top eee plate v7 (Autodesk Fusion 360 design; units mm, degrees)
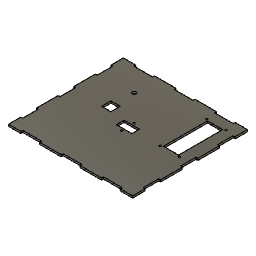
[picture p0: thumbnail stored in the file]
sketch "Sketch1" plane through (0, 0, 0) normal (0, 0, 1) x axis (1, 0, 0)
  line L1 (-100, 92.5) -> (100, 92.5)
  line L2 (-100, -92.5) -> (-100, 92.5)
  line L3 (100, -92.5) -> (-100, -92.5)
  line L4 (100, 92.5) -> (100, -92.5)
  line L5 (-100, -92.5) -> (100, 92.5)
  line L6 (100, -92.5) -> (-100, 92.5)
  point P6 (0, 0)
  point P1 (0, 0)
  point P4 (-100, -92.5)
  point P5 (100, -92.5)
  point P3 (-100, 92.5)
  point P2 (100, 92.5)
  perpendicular L1 L2
  parallel L1 L3
  parallel L2 L4
  horizontal L1
  coincident L5 P6
  coincident L6 P6
  coincident P1 P6
  dimension "d1" distance P4 P5 = 200
  dimension "d2" distance P3 P4 = 185
  dimension "d28" distance P2 = 15
extrude "Extrude1" new body sketch "Sketch1" profile of L1 L2 L3 L4 along normal blind 3
sketch "Sketch2" plane through (0, 0, 3) normal (0, 0, 1) x axis (-1, 0, 0)
  line L1 (-100, -92.5) -> (-100, 92.5)
  line L2 (100, -92.5) -> (-100, -92.5)
  line L3 (100, 92.5) -> (100, -92.5)
  line L4 (50, 92.5) -> (80, 92.5)
  line L5 (50, 89.5) -> (50, 92.5)
  line L6 (80, 89.5) -> (50, 89.5)
  line L7 (80, 92.5) -> (80, 89.5)
  line L8 (-15, 92.5) -> (15, 92.5)
  line L9 (-15, 89.5) -> (-15, 92.5)
  line L10 (15, 89.5) -> (-15, 89.5)
  line L11 (15, 92.5) -> (15, 89.5)
  line L12 (-80, 92.5) -> (-50, 92.5)
  line L13 (-80, 89.5) -> (-80, 92.5)
  line L14 (-50, 89.5) -> (-80, 89.5)
  line L15 (-50, 92.5) -> (-50, 89.5)
  line L16 (-100, 92.5) -> (100, 92.5)
  point P6 (80, 92.5)
  point P9 (80, 89.5)
  point P18 (100, 92.5)
  point P7 (50, 92.5)
  point P10 (15, 92.5)
  point P11 (-15, 92.5)
  point P12 (-15, 89.5)
  point P14 (-50, 92.5)
  point P15 (-80, 92.5)
  point P19 (-100, 92.5)
  horizontal L4
  vertical L5
  horizontal L6
  vertical L7
  horizontal L8
  vertical L9
  horizontal L10
  vertical L11
  horizontal L12
  vertical L13
  horizontal L14
  vertical L15
  equal L7 L11
  equal L11 L15
  collinear L8 L12
  collinear L8 L16
  collinear L4 L16
  dimension "d5" distance P6 P9 = 3
  dimension "d6" distance P6 P18 = 20
  dimension "d7" distance P6 P7 = 30
  dimension "d8" distance P7 P10 = 35
  dimension "d9" distance P10 P11 = 30
  dimension "d10" distance P12 P14 = 35
  dimension "d11" distance P14 P15 = 30
  dimension "d12" distance P15 P19 = 20
extrude "Extrude2" cut sketch "Sketch2" profile of L4 L5 L6 L7 L8 L9 L10 L11 L12 L13 L14 L15 L16 against normal blind 20
mirror "Mirror1"
sketch "Sketch3" plane through (0, 0, 3) normal (0, 0, 1) x axis (-1, 0, 0)
  line L1 (50, -89.5) -> (50, -92.5)
  line L2 (80, -89.5) -> (50, -89.5)
  line L3 (80, -92.5) -> (80, -89.5)
  line L4 (100, -92.5) -> (80, -92.5)
  line L5 (100, 92.5) -> (100, -92.5)
  line L6 (80, 92.5) -> (100, 92.5)
  line L7 (80, 89.5) -> (80, 92.5)
  line L8 (50, 89.5) -> (80, 89.5)
  line L9 (50, 92.5) -> (50, 89.5)
  line L10 (15, 92.5) -> (50, 92.5)
  line L11 (15, 89.5) -> (15, 92.5)
  line L12 (-15, 89.5) -> (15, 89.5)
  line L13 (-15, 92.5) -> (-15, 89.5)
  line L14 (-50, 92.5) -> (-15, 92.5)
  line L15 (-50, 89.5) -> (-50, 92.5)
  line L16 (-80, 89.5) -> (-50, 89.5)
  line L17 (-80, 92.5) -> (-80, 89.5)
  line L18 (-100, 92.5) -> (-80, 92.5)
  line L19 (-100, -92.5) -> (-100, 92.5)
  line L20 (-80, -92.5) -> (-100, -92.5)
  line L21 (-80, -89.5) -> (-80, -92.5)
  line L22 (-50, -89.5) -> (-80, -89.5)
  line L23 (-50, -92.5) -> (-50, -89.5)
  line L24 (-15, -92.5) -> (-50, -92.5)
  line L25 (-15, -89.5) -> (-15, -92.5)
  line L26 (15, -89.5) -> (-15, -89.5)
  line L27 (15, -92.5) -> (15, -89.5)
  line L28 (50, -92.5) -> (15, -92.5)
  line L29 (97, 72.5) -> (100, 72.5)
  line L30 (97, 47.5) -> (97, 72.5)
  line L31 (100, 47.5) -> (97, 47.5)
  line L32 (100, 72.5) -> (100, 47.5)
  line L33 (97, 12.5) -> (100, 12.5)
  line L34 (97, -12.5) -> (97, 12.5)
  line L35 (100, -12.5) -> (97, -12.5)
  line L36 (100, 12.5) -> (100, -12.5)
  line L37 (97, -47.5) -> (100, -47.5)
  line L38 (97, -72.5) -> (97, -47.5)
  line L39 (100, -72.5) -> (97, -72.5)
  line L40 (100, -47.5) -> (100, -72.5)
  point P30 (100, 72.5)
  point P34 (100, 12.5)
  point P38 (100, -47.5)
  point P6 (100, -92.5)
  point P41 (100, -72.5)
  horizontal L29
  vertical L30
  horizontal L31
  vertical L32
  coincident L5 P30
  horizontal L33
  vertical L34
  horizontal L35
  vertical L36
  coincident L5 P34
  horizontal L37
  vertical L38
  horizontal L39
  vertical L40
  coincident L5 P38
  equal L35 L39
  equal L31 L35
  dimension "d16" distance P6 P41 = 20
  dimension "d17" distance L37 L39 = 25
  dimension "d18" distance L35 L37 = 35
  dimension "d19" distance L33 L35 = 25
  dimension "d20" distance L31 L33 = 35
  dimension "d21" distance P30 L31 = 25
  dimension "d22" distance L6 L29 = 20
  dimension "d23" distance L38 L40 = 3
extrude "Extrude3" cut sketch "Sketch3" profile of L5 L29 L30 L31 L32 L33 L34 L35 L36 L37 L38 L39 L40 against normal blind 20
mirror "Mirror2"
sketch "Sketch4" plane through (0, 0, 3) normal (0, 0, 1) x axis (-1, 0, 0)
  line L1 (-100, 47.5) -> (-97, 47.5)
  line L2 (-100, 12.5) -> (-100, 47.5)
  line L3 (-97, 12.5) -> (-100, 12.5)
  line L4 (-97, -12.5) -> (-97, 12.5)
  line L5 (-100, -12.5) -> (-97, -12.5)
  line L6 (-100, -47.5) -> (-100, -12.5)
  line L7 (-97, -47.5) -> (-100, -47.5)
  line L8 (-97, -72.5) -> (-97, -47.5)
  line L9 (-100, -72.5) -> (-97, -72.5)
  line L10 (-100, -92.5) -> (-100, -72.5)
  line L11 (-80, -92.5) -> (-100, -92.5)
  line L12 (-80, -89.5) -> (-80, -92.5)
  line L13 (-50, -89.5) -> (-80, -89.5)
  line L14 (-50, -92.5) -> (-50, -89.5)
  line L15 (-15, -92.5) -> (-50, -92.5)
  line L16 (-15, -89.5) -> (-15, -92.5)
  line L17 (15, -89.5) -> (-15, -89.5)
  line L18 (15, -92.5) -> (15, -89.5)
  line L19 (50, -92.5) -> (15, -92.5)
  line L20 (50, -89.5) -> (50, -92.5)
  line L21 (80, -89.5) -> (50, -89.5)
  line L22 (80, -92.5) -> (80, -89.5)
  line L23 (100, -92.5) -> (80, -92.5)
  line L24 (100, -72.5) -> (100, -92.5)
  line L25 (97, -72.5) -> (100, -72.5)
  line L26 (97, -47.5) -> (97, -72.5)
  line L27 (100, -47.5) -> (97, -47.5)
  line L28 (100, -12.5) -> (100, -47.5)
  line L29 (97, -12.5) -> (100, -12.5)
  line L30 (97, 12.5) -> (97, -12.5)
  line L31 (100, 12.5) -> (97, 12.5)
  line L32 (100, 47.5) -> (100, 12.5)
  line L33 (97, 47.5) -> (100, 47.5)
  line L34 (97, 72.5) -> (97, 47.5)
  line L35 (100, 72.5) -> (97, 72.5)
  line L36 (100, 92.5) -> (100, 72.5)
  line L37 (80, 92.5) -> (100, 92.5)
  line L38 (80, 89.5) -> (80, 92.5)
  line L39 (50, 89.5) -> (80, 89.5)
  line L40 (50, 92.5) -> (50, 89.5)
  line L41 (15, 92.5) -> (50, 92.5)
  line L42 (15, 89.5) -> (15, 92.5)
  line L43 (-15, 89.5) -> (15, 89.5)
  line L44 (-15, 92.5) -> (-15, 89.5)
  line L45 (-50, 92.5) -> (-15, 92.5)
  line L46 (-50, 89.5) -> (-50, 92.5)
  line L47 (-80, 89.5) -> (-50, 89.5)
  line L48 (-80, 92.5) -> (-80, 89.5)
  line L49 (-100, 92.5) -> (-80, 92.5)
  line L50 (-100, 72.5) -> (-100, 92.5)
  line L51 (-97, 72.5) -> (-100, 72.5)
  line L52 (-97, 47.5) -> (-97, 72.5)
  line L53 (35, -22.5) -> (50, -22.5)
  line L54 (35, -7.5) -> (35, -22.5)
  line L55 (50, -7.5) -> (35, -7.5)
  line L56 (50, -22.5) -> (50, -7.5)
  point P56 (35, -7.5)
  point P57 (50, -7.5)
  point P55 (35, -22.5)
  horizontal L53
  vertical L54
  horizontal L55
  vertical L56
  dimension "d27" distance P56 P57 = 15
  dimension "d28" distance P55 P56 = 15
  dimension "d29" distance L41 L55 = 100
  dimension "d30" distance L28 L56 = 50
extrude "Extrude4" cut sketch "Sketch4" profile of L53 L54 L55 L56 against normal blind 20
sketch "Sketch5" plane through (0, 0, 3) normal (0, 0, 1) x axis (-1, 0, 0)
  line L1 (35, -7.5) -> (35, -22.5)
  line L2 (50, -7.5) -> (35, -7.5)
  line L3 (50, -22.5) -> (50, -7.5)
  line L4 (35, -22.5) -> (50, -22.5)
  line L5 (-100, 47.5) -> (-97, 47.5)
  line L6 (-100, 12.5) -> (-100, 47.5)
  line L7 (-97, 12.5) -> (-100, 12.5)
  line L8 (-97, -12.5) -> (-97, 12.5)
  line L9 (-100, -12.5) -> (-97, -12.5)
  line L10 (-100, -47.5) -> (-100, -12.5)
  line L11 (-97, -47.5) -> (-100, -47.5)
  line L12 (-97, -72.5) -> (-97, -47.5)
  line L13 (-100, -72.5) -> (-97, -72.5)
  line L14 (-100, -92.5) -> (-100, -72.5)
  line L15 (-80, -92.5) -> (-100, -92.5)
  line L16 (-80, -89.5) -> (-80, -92.5)
  line L17 (-50, -89.5) -> (-80, -89.5)
  line L18 (-50, -92.5) -> (-50, -89.5)
  line L19 (-15, -92.5) -> (-50, -92.5)
  line L20 (-15, -89.5) -> (-15, -92.5)
  line L21 (15, -89.5) -> (-15, -89.5)
  line L22 (15, -92.5) -> (15, -89.5)
  line L23 (50, -92.5) -> (15, -92.5)
  line L24 (50, -89.5) -> (50, -92.5)
  line L25 (80, -89.5) -> (50, -89.5)
  line L26 (80, -92.5) -> (80, -89.5)
  line L27 (100, -92.5) -> (80, -92.5)
  line L28 (100, -72.5) -> (100, -92.5)
  line L29 (97, -72.5) -> (100, -72.5)
  line L30 (97, -47.5) -> (97, -72.5)
  line L31 (100, -47.5) -> (97, -47.5)
  line L32 (100, -12.5) -> (100, -47.5)
  line L33 (97, -12.5) -> (100, -12.5)
  line L34 (97, 12.5) -> (97, -12.5)
  line L35 (100, 12.5) -> (97, 12.5)
  line L36 (100, 47.5) -> (100, 12.5)
  line L37 (97, 47.5) -> (100, 47.5)
  line L38 (97, 72.5) -> (97, 47.5)
  line L39 (100, 72.5) -> (97, 72.5)
  line L40 (100, 92.5) -> (100, 72.5)
  line L41 (80, 92.5) -> (100, 92.5)
  line L42 (80, 89.5) -> (80, 92.5)
  line L43 (50, 89.5) -> (80, 89.5)
  line L44 (50, 92.5) -> (50, 89.5)
  line L45 (15, 92.5) -> (50, 92.5)
  line L46 (15, 89.5) -> (15, 92.5)
  line L47 (-15, 89.5) -> (15, 89.5)
  line L48 (-15, 92.5) -> (-15, 89.5)
  line L49 (-50, 92.5) -> (-15, 92.5)
  line L50 (-50, 89.5) -> (-50, 92.5)
  line L51 (-80, 89.5) -> (-50, 89.5)
  line L52 (-80, 92.5) -> (-80, 89.5)
  line L53 (-100, 92.5) -> (-80, 92.5)
  line L54 (-100, 72.5) -> (-100, 92.5)
  line L55 (-97, 72.5) -> (-100, 72.5)
  line L56 (-97, 47.5) -> (-97, 72.5)
  line L57 (12.5, -6.15) -> (-12.5, -6.15)
  line L58 (12.5, 6.15) -> (12.5, -6.15)
  line L59 (-12.5, 6.15) -> (12.5, 6.15)
  line L60 (-12.5, -6.15) -> (-12.5, 6.15)
  line L61 (12.5, 6.15) -> (-12.5, -6.15)
  line L62 (-12.5, 6.15) -> (12.5, -6.15)
  point P62 (0, 0)
  point P1 (0, 0)
  point P60 (12.5, 6.15)
  point P61 (-12.5, 6.15)
  perpendicular L57 L58
  parallel L57 L59
  parallel L58 L60
  horizontal L57
  coincident L61 P62
  coincident L62 P62
  coincident P1 P62
  dimension "d33" distance L57 L59 = 12.3
  dimension "d34" distance P60 P61 = 25
extrude "Extrude5" cut sketch "Sketch5" profile of L57 L58 L59 L60 against normal blind 15
sketch "Sketch6" plane through (0, 0, 3) normal (0, 0, 1) x axis (-1, 0, 0)
  line L1 (-12.5, -6.15) -> (12.5, -6.15)
  line L2 (-12.5, 6.15) -> (-12.5, -6.15)
  line L3 (12.5, 6.15) -> (-12.5, 6.15)
  line L4 (12.5, -6.15) -> (12.5, 6.15)
  line L5 (35, -7.5) -> (35, -22.5)
  line L6 (50, -7.5) -> (35, -7.5)
  line L7 (50, -22.5) -> (50, -7.5)
  line L8 (35, -22.5) -> (50, -22.5)
  line L9 (-100, 47.5) -> (-97, 47.5)
  line L10 (-100, 12.5) -> (-100, 47.5)
  line L11 (-97, 12.5) -> (-100, 12.5)
  line L12 (-97, -12.5) -> (-97, 12.5)
  line L13 (-100, -12.5) -> (-97, -12.5)
  line L14 (-100, -47.5) -> (-100, -12.5)
  line L15 (-97, -47.5) -> (-100, -47.5)
  line L16 (-97, -72.5) -> (-97, -47.5)
  line L17 (-100, -72.5) -> (-97, -72.5)
  line L18 (-100, -92.5) -> (-100, -72.5)
  line L19 (-80, -92.5) -> (-100, -92.5)
  line L20 (-80, -89.5) -> (-80, -92.5)
  line L21 (-50, -89.5) -> (-80, -89.5)
  line L22 (-50, -92.5) -> (-50, -89.5)
  line L23 (-15, -92.5) -> (-50, -92.5)
  line L24 (-15, -89.5) -> (-15, -92.5)
  line L25 (15, -89.5) -> (-15, -89.5)
  line L26 (15, -92.5) -> (15, -89.5)
  line L27 (50, -92.5) -> (15, -92.5)
  line L28 (50, -89.5) -> (50, -92.5)
  line L29 (80, -89.5) -> (50, -89.5)
  line L30 (80, -92.5) -> (80, -89.5)
  line L31 (100, -92.5) -> (80, -92.5)
  line L32 (100, -72.5) -> (100, -92.5)
  line L33 (97, -72.5) -> (100, -72.5)
  line L34 (97, -47.5) -> (97, -72.5)
  line L35 (100, -47.5) -> (97, -47.5)
  line L36 (100, -12.5) -> (100, -47.5)
  line L37 (97, -12.5) -> (100, -12.5)
  line L38 (97, 12.5) -> (97, -12.5)
  line L39 (100, 12.5) -> (97, 12.5)
  line L40 (100, 47.5) -> (100, 12.5)
  line L41 (97, 47.5) -> (100, 47.5)
  line L42 (97, 72.5) -> (97, 47.5)
  line L43 (100, 72.5) -> (97, 72.5)
  line L44 (100, 92.5) -> (100, 72.5)
  line L45 (80, 92.5) -> (100, 92.5)
  line L46 (80, 89.5) -> (80, 92.5)
  line L47 (50, 89.5) -> (80, 89.5)
  line L48 (50, 92.5) -> (50, 89.5)
  line L49 (15, 92.5) -> (50, 92.5)
  line L50 (15, 89.5) -> (15, 92.5)
  line L51 (-15, 89.5) -> (15, 89.5)
  line L52 (-15, 92.5) -> (-15, 89.5)
  line L53 (-50, 92.5) -> (-15, 92.5)
  line L54 (-50, 89.5) -> (-50, 92.5)
  line L55 (-80, 89.5) -> (-50, 89.5)
  line L56 (-80, 92.5) -> (-80, 89.5)
  line L57 (-100, 92.5) -> (-80, 92.5)
  line L58 (-100, 72.5) -> (-100, 92.5)
  line L59 (-97, 72.5) -> (-100, 72.5)
  line L60 (-97, 47.5) -> (-97, 72.5)
  line L61 (0, -10) -> (0, 0)
  circle C1 centre (0, -10) radius 1.5
  point P1 (0, 0)
  point P62 (0, 0)
  point P63 (0, -10)
  point P64 (0, -10)
  coincident P1 P62
  perpendicular L6 L61
  coincident P63 P64
  dimension "d37" distance P62 P63 = 10
  dimension "d38" diameter C1 = 3
extrude "Extrude6" cut sketch "Sketch6" profile of C1 against normal blind 10
mirror "Mirror3"
sketch "Sketch7" plane through (0, 0, 3) normal (0, 0, 1) x axis (-1, 0, 0)
  line L1 (-12.5, -6.15) -> (12.5, -6.15)
  line L2 (-12.5, 6.15) -> (-12.5, -6.15)
  line L3 (12.5, 6.15) -> (-12.5, 6.15)
  line L4 (12.5, -6.15) -> (12.5, 6.15)
  line L5 (35, -7.5) -> (35, -22.5)
  line L6 (50, -7.5) -> (35, -7.5)
  line L7 (50, -22.5) -> (50, -7.5)
  line L8 (35, -22.5) -> (50, -22.5)
  line L9 (-100, 47.5) -> (-97, 47.5)
  line L10 (-100, 12.5) -> (-100, 47.5)
  line L11 (-97, 12.5) -> (-100, 12.5)
  line L12 (-97, -12.5) -> (-97, 12.5)
  line L13 (-100, -12.5) -> (-97, -12.5)
  line L14 (-100, -47.5) -> (-100, -12.5)
  line L15 (-97, -47.5) -> (-100, -47.5)
  line L16 (-97, -72.5) -> (-97, -47.5)
  line L17 (-100, -72.5) -> (-97, -72.5)
  line L18 (-100, -92.5) -> (-100, -72.5)
  line L19 (-80, -92.5) -> (-100, -92.5)
  line L20 (-80, -89.5) -> (-80, -92.5)
  line L21 (-50, -89.5) -> (-80, -89.5)
  line L22 (-50, -92.5) -> (-50, -89.5)
  line L23 (-15, -92.5) -> (-50, -92.5)
  line L24 (-15, -89.5) -> (-15, -92.5)
  line L25 (15, -89.5) -> (-15, -89.5)
  line L26 (15, -92.5) -> (15, -89.5)
  line L27 (50, -92.5) -> (15, -92.5)
  line L28 (50, -89.5) -> (50, -92.5)
  line L29 (80, -89.5) -> (50, -89.5)
  line L30 (80, -92.5) -> (80, -89.5)
  line L31 (100, -92.5) -> (80, -92.5)
  line L32 (100, -72.5) -> (100, -92.5)
  line L33 (97, -72.5) -> (100, -72.5)
  line L34 (97, -47.5) -> (97, -72.5)
  line L35 (100, -47.5) -> (97, -47.5)
  line L36 (100, -12.5) -> (100, -47.5)
  line L37 (97, -12.5) -> (100, -12.5)
  line L38 (97, 12.5) -> (97, -12.5)
  line L39 (100, 12.5) -> (97, 12.5)
  line L40 (100, 47.5) -> (100, 12.5)
  line L41 (97, 47.5) -> (100, 47.5)
  line L42 (97, 72.5) -> (97, 47.5)
  line L43 (100, 72.5) -> (97, 72.5)
  line L44 (100, 92.5) -> (100, 72.5)
  line L45 (80, 92.5) -> (100, 92.5)
  line L46 (80, 89.5) -> (80, 92.5)
  line L47 (50, 89.5) -> (80, 89.5)
  line L48 (50, 92.5) -> (50, 89.5)
  line L49 (15, 92.5) -> (50, 92.5)
  line L50 (15, 89.5) -> (15, 92.5)
  line L51 (-15, 89.5) -> (15, 89.5)
  line L52 (-15, 92.5) -> (-15, 89.5)
  line L53 (-50, 92.5) -> (-15, 92.5)
  line L54 (-50, 89.5) -> (-50, 92.5)
  line L55 (-80, 89.5) -> (-50, 89.5)
  line L56 (-80, 92.5) -> (-80, 89.5)
  line L57 (-100, 92.5) -> (-80, 92.5)
  line L58 (-100, 72.5) -> (-100, 92.5)
  line L59 (-97, 72.5) -> (-100, 72.5)
  line L60 (-97, 47.5) -> (-97, 72.5)
  line L61 (30, -30) -> (-30, -30)
  line L62 (30, 30) -> (30, -30)
  line L63 (-30, 30) -> (30, 30)
  line L64 (-30, -30) -> (-30, 30)
  line L65 (30, 30) -> (-30, -30)
  line L66 (-30, 30) -> (30, -30)
  line L67 (-80, -72.5) -> (-55.6, -72.5)
  line L68 (-80, -1.5) -> (-80, -72.5)
  line L69 (-55.6, -1.5) -> (-80, -1.5)
  line L70 (-55.6, -72.5) -> (-55.6, -1.5)
  line L71 (47.1854, 4.2838) -> (89.1854, 4.2838)
  line L72 (47.1854, 80.2838) -> (47.1854, 4.2838)
  line L73 (89.1854, 80.2838) -> (47.1854, 80.2838)
  line L74 (89.1854, 4.2838) -> (89.1854, 80.2838)
  line L75 (-80, -1.5) -> (-55.6, -72.5)
  line L76 (-80, -72.5) -> (-55.6, -1.5)
  line L77 (-49.8, 3) -> (-85.8, 3)
  line L78 (-49.8, -77) -> (-49.8, 3)
  line L79 (-85.8, -77) -> (-49.8, -77)
  line L80 (-85.8, 3) -> (-85.8, -77)
  line L81 (-49.8, -77) -> (-85.8, 3)
  line L82 (-85.8, -77) -> (-49.8, 3)
  line L83 (42.5, -52.5) -> (42.5, -22.5)
  circle C1 centre (0, 10) radius 1.5
  circle C2 centre (0, -10) radius 1.5
  circle C3 centre (-52.3, -74.5) radius 1.5
  circle C4 centre (-83.3, -74.5) radius 1.5
  circle C5 centre (-52.3, 0.5) radius 1.5
  circle C6 centre (-83.3, 0.5) radius 1.5
  circle C7 centre (42.5, -52.5) radius 3
  point P68 (0, 0)
  point P1 (0, 0)
  point P81 (-67.8, -37)
  point P86 (42.5, -22.5)
  point P87 (42.5, -52.5)
  point P88 (42.5, -52.5)
  point P66 (30, 30)
  point P67 (-30, 30)
  point P65 (30, -30)
  point P70 (-80, -72.5)
  point P71 (-80, -1.5)
  point P69 (-55.6, -72.5)
  point P73 (89.1854, 4.2838)
  point P74 (47.1854, 4.2838)
  point P76 (89.1854, 80.2838)
  point P79 (-49.8, -77)
  point P80 (-85.8, -77)
  point P78 (-49.8, 3)
  point P82 (-52.3, -74.5)
  point P83 (-83.3, -74.5)
  point P84 (-52.3, 0.5)
  point P85 (-83.3, 0.5)
  perpendicular L61 L62
  parallel L61 L63
  parallel L62 L64
  horizontal L61
  coincident L65 P68
  coincident L66 P68
  coincident P1 P68
  horizontal L67
  vertical L68
  horizontal L69
  vertical L70
  horizontal L71
  vertical L72
  horizontal L73
  vertical L74
  perpendicular L77 L78
  parallel L77 L79
  parallel L78 L80
  horizontal L77
  coincident L81 P81
  coincident L82 P81
  midpoint L76 P81
  midpoint L8 P86
  perpendicular L8 L83
  coincident P87 P88
  dimension "d42" distance P66 P67 = 60
  dimension "d43" distance P65 P66 = 60
  dimension "d44" distance P70 P71 = 71
  dimension "d45" distance P69 P70 = 24.4
  dimension "d46" distance P73 P74 = 42
  dimension "d47" distance P73 P76 = 76
  dimension "d48" distance L19 L67 = 20
  dimension "d49" distance L14 L68 = 20
  dimension "d52" distance P79 P80 = 36
  dimension "d53" distance P78 P79 = 80
  dimension "d54" diameter C3 = 3
  dimension "d55" distance L78 P82 = 2.5
  dimension "d56" distance L79 P82 = 2.5
  dimension "d57" diameter C4 = 3
  dimension "d58" distance L79 P83 = 2.5
  dimension "d59" distance L80 P83 = 2.5
  dimension "d60" diameter C5 = 3
  dimension "d61" distance L77 P84 = 2.5
  dimension "d62" distance L78 P84 = 2.5
  dimension "d63" diameter C6 = 3
  dimension "d64" distance L77 P85 = 2.5
  dimension "d65" distance L80 P85 = 2.5
  dimension "d66" distance P86 P87 = 30
  dimension "d67" diameter C7 = 6
extrude "Extrude7" cut sketch "Sketch7" profile of L67 L68 L69 L70 C3 C4 C5 C6 C7 against normal blind 40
